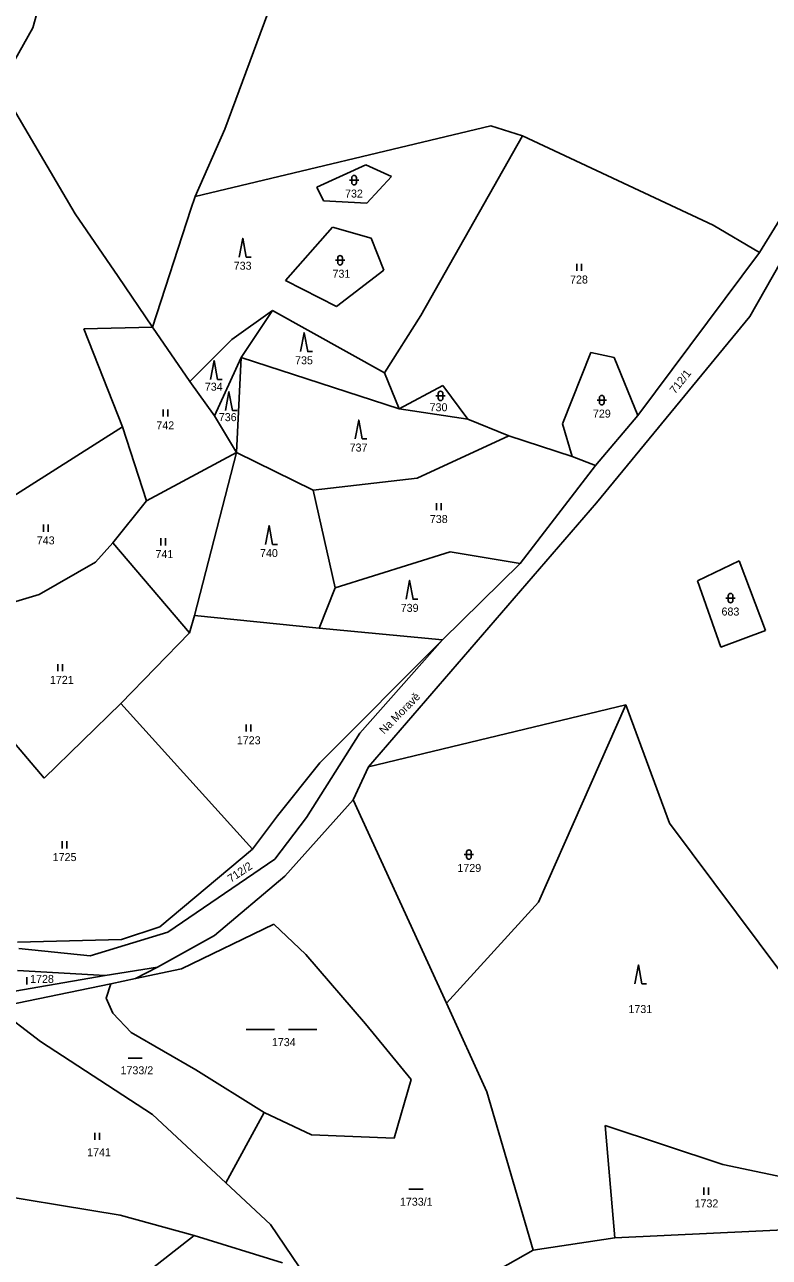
# Model space of a CAD drawing. Extents: x -670359 to -668019, y -978807 to -976674.
# Drawn here: x -668799.4 to -668641.1, y -978050.6 to -977788.7 of the extents above; entities that cross this region are included whole.
import ezdxf

# ---------------------------------------------------------------- set-up
doc = ezdxf.new("R2010")
doc.units = 0
for name, color, linetype in [('Hranice kat_území', 7, 'Continuous'), ('Hranice parcel', 7, 'Continuous'), ('Parcelní čísla', 7, 'Continuous'), ('Pop  PČ popisy', 7, 'Continuous'), ('Značky kultur', 7, 'Continuous')]:
    doc.layers.add(name, color=color, linetype=linetype)

msp = doc.modelspace()

# ---------------------------------------------------------------- linework, layer by layer
at = {"layer": 'Hranice kat_území'}
for points in [[(-668673.95, -978046.48), (-668633.57, -978044.55)], [(-668691.36, -978049.13), (-668673.95, -978046.48)], [(-668717.71, -978064.03), (-668691.36, -978049.13)]]:
    msp.add_lwpolyline(points, dxfattribs=at)
at = {"layer": 'Hranice parcel'}
for points in [[(-668793.42, -977774.28), (-668797.64, -977789.39)], [(-668743.95, -977776.09), (-668756.86, -977810.95)], [(-668797.64, -977789.39), (-668804.65, -977801.77)], [(-668804.65, -977801.77), (-668788.64, -977828.94)], [(-668763.15, -977825.26), (-668700.35, -977810.2)], [(-668756.86, -977810.95), (-668763.15, -977825.26)], [(-668700.35, -977810.2), (-668693.6, -977812.35)], [(-668693.6, -977812.35), (-668715.21, -977850.5)], [(-668693.6, -977812.35), (-668653.1, -977831.31)], [(-668737.3, -977823.25), (-668726.9, -977818.5)], [(-668726.9, -977818.5), (-668721.45, -977820.95)], [(-668721.45, -977820.95), (-668726.65, -977826.65)], [(-668735.85, -977826.15), (-668737.3, -977823.25)], [(-668764.06, -977827.89), (-668763.15, -977825.26)], [(-668726.65, -977826.65), (-668735.85, -977826.15)], [(-668636.27, -977825.84), (-668643.27, -977837.1)], [(-668772.17, -977852.97), (-668779.51, -977842.25), (-668788.64, -977828.94)], [(-668772.17, -977852.97), (-668764.06, -977827.89)], [(-668743.93, -977843.06), (-668733.97, -977831.73)], [(-668733.97, -977831.73), (-668725.73, -977834.07)], [(-668653.1, -977831.31), (-668643.27, -977837.1)], [(-668725.73, -977834.07), (-668723.03, -977840.88)], [(-668643.27, -977837.1), (-668669.09, -977871.75)], [(-668645.3, -977850.7), (-668638.79, -977839.27)], [(-668723.03, -977840.88), (-668733.14, -977848.61)], [(-668733.14, -977848.61), (-668743.93, -977843.06)], [(-668746.68, -977849.45), (-668755.34, -977855.59)], [(-668753.36, -977859.44), (-668746.68, -977849.45)], [(-668746.68, -977849.45), (-668722.94, -977862.72)], [(-668715.21, -977850.5), (-668722.94, -977862.72)], [(-668677.85, -977890.29), (-668645.3, -977850.7)], [(-668772.17, -977852.97), (-668786.8, -977853.34)], [(-668786.8, -977853.34), (-668778.55, -977874.17)], [(-668772.17, -977852.97), (-668764.26, -977864.53)], [(-668755.34, -977855.59), (-668764.26, -977864.53)], [(-668685.11, -977873.55), (-668679.05, -977858.36)], [(-668679.05, -977858.36), (-668674.09, -977859.42)], [(-668753.36, -977859.44), (-668759, -977871.82)], [(-668754.38, -977879.6), (-668753.36, -977859.44)], [(-668753.36, -977859.44), (-668719.76, -977870.33)], [(-668674.09, -977859.42), (-668669.09, -977871.75)], [(-668722.94, -977862.72), (-668719.76, -977870.33)], [(-668764.26, -977864.53), (-668759, -977871.82)], [(-668719.76, -977870.33), (-668710.54, -977865.4)], [(-668710.54, -977865.4), (-668705.2, -977872.53)], [(-668719.76, -977870.33), (-668705.2, -977872.53)], [(-668818.99, -977899.82), (-668778.55, -977874.17)], [(-668778.55, -977874.17), (-668773.47, -977889.86)], [(-668759, -977871.82), (-668754.38, -977879.6)], [(-668705.2, -977872.53), (-668696.48, -977876.08)], [(-668683.05, -977880.51), (-668685.11, -977873.55)], [(-668669.09, -977871.75), (-668678.09, -977882.37)], [(-668715.97, -977885.06), (-668696.48, -977876.08)], [(-668696.48, -977876.08), (-668683.05, -977880.51)], [(-668773.47, -977889.86), (-668754.38, -977879.6)], [(-668754.38, -977879.6), (-668763.31, -977914.29)], [(-668754.38, -977879.6), (-668738.08, -977887.64)], [(-668683.05, -977880.51), (-668678.09, -977882.37)], [(-668678.09, -977882.37), (-668694.09, -977903.2)], [(-668738.08, -977887.64), (-668715.97, -977885.06)], [(-668773.47, -977889.86), (-668780.63, -977898.8)], [(-668738.08, -977887.64), (-668733.42, -977908.38)], [(-668726.28, -977946.45), (-668677.85, -977890.29)], [(-668780.63, -977898.8), (-668784.33, -977902.95)], [(-668764.36, -977917.97), (-668780.63, -977898.8)], [(-668784.33, -977902.95), (-668796.28, -977909.8)], [(-668733.42, -977908.38), (-668708.98, -977900.76)], [(-668708.98, -977900.76), (-668694.09, -977903.2)], [(-668656.41, -977906.89), (-668647.53, -977902.64)], [(-668647.53, -977902.64), (-668641.97, -977917.48)], [(-668694.09, -977903.2), (-668710.56, -977919.4)], [(-668733.42, -977908.38), (-668736.81, -977916.93)], [(-668651.46, -977920.99), (-668656.41, -977906.89)], [(-668796.28, -977909.8), (-668818.56, -977916.46)], [(-668763.31, -977914.29), (-668764.36, -977917.97)], [(-668736.81, -977916.93), (-668763.31, -977914.29)], [(-668764.36, -977917.97), (-668778.92, -977932.96)], [(-668710.56, -977919.4), (-668736.81, -977916.93)], [(-668641.97, -977917.48), (-668651.46, -977920.99)], [(-668710.56, -977919.4), (-668736.63, -977945.54)], [(-668728.17, -977939.29), (-668710.56, -977919.4)], [(-668778.92, -977932.96), (-668795.2, -977948.83)], [(-668778.92, -977932.96), (-668750.96, -977963.93)], [(-668671.67, -977933.25), (-668726.28, -977946.45)], [(-668671.67, -977933.25), (-668690.16, -977975.16)], [(-668671.67, -977933.25), (-668662.34, -977958.37)], [(-668795.2, -977948.83), (-668806.66, -977935.37)], [(-668739.51, -977957.21), (-668728.17, -977939.29)], [(-668736.63, -977945.54), (-668745.63, -977956.82)], [(-668726.28, -977946.45), (-668729.57, -977953.43)], [(-668729.57, -977953.43), (-668744.09, -977969.65)], [(-668709.74, -977996.65), (-668729.57, -977953.43)], [(-668745.63, -977956.82), (-668750.96, -977963.93)], [(-668746.24, -977966.01), (-668739.51, -977957.21)], [(-668662.34, -977958.37), (-668619.62, -978015.52)], [(-668750.96, -977963.93), (-668770.61, -977980.38)], [(-668768.91, -977981.53), (-668746.24, -977966.01)], [(-668744.09, -977969.65), (-668759.04, -977982.26)], [(-668690.16, -977975.16), (-668709.74, -977996.65)], [(-668785.48, -977986.54), (-668768.91, -977981.53)], [(-668770.61, -977980.38), (-668778.82, -977983.12)], [(-668766.04, -977989.34), (-668746.43, -977979.85)], [(-668746.43, -977979.85), (-668739.66, -977986.29)], [(-668778.82, -977983.12), (-668800.92, -977983.69)], [(-668759.04, -977982.26), (-668771.16, -977989.01)], [(-668800.6, -977985.03), (-668785.48, -977986.54)], [(-668739.66, -977986.29), (-668726.95, -978000.99)], [(-668771.16, -977989.01), (-668782.24, -977990.74)], [(-668775.85, -977991.41), (-668771.16, -977989.01)], [(-668775.85, -977991.41), (-668766.04, -977989.34)], [(-668782.24, -977990.74), (-668801.42, -977994.08)], [(-668782.24, -977990.74), (-668800.87, -977989.69)], [(-668781.08, -977992.49), (-668775.85, -977991.41)], [(-668805.49, -977997.52), (-668781.08, -977992.49)], [(-668776.74, -978002.88), (-668780.62, -977998.76), (-668782.03, -977995.6), (-668781.08, -977992.49)], [(-668701.18, -978015.44), (-668709.74, -977996.65)], [(-668796.01, -978004.81), (-668805.49, -977997.52)], [(-668726.95, -978000.99), (-668717.23, -978012.84)], [(-668772.18, -978020.27), (-668796.01, -978004.81)], [(-668762.97, -978010.83), (-668776.74, -978002.88)], [(-668748.48, -978019.89), (-668762.97, -978010.83)], [(-668717.23, -978012.84), (-668720.88, -978025.33)], [(-668691.36, -978049.13), (-668701.18, -978015.44)], [(-668772.18, -978020.27), (-668756.62, -978034.81)], [(-668756.62, -978034.81), (-668748.48, -978019.89)], [(-668738.4, -978024.63), (-668748.48, -978019.89)], [(-668651.02, -978030.89), (-668676.01, -978022.61)], [(-668676.01, -978022.61), (-668673.95, -978046.48)], [(-668720.88, -978025.33), (-668738.4, -978024.63)], [(-668634.2, -978034.46), (-668651.02, -978030.89)], [(-668779.04, -978041.67), (-668811.76, -978036.29)], [(-668747.13, -978043.67), (-668756.62, -978034.81)], [(-668763.34, -978046.02), (-668779.04, -978041.67)], [(-668741.05, -978052.66), (-668747.13, -978043.67)], [(-668763.34, -978046.02), (-668795.8, -978071.45)], [(-668744.55, -978051.8), (-668763.34, -978046.02)]]:
    msp.add_lwpolyline(points, dxfattribs=at)
at = {"layer": 'Značky kultur'}
for p, q in [((-668730.37, -977821.76), (-668728.37, -977821.76)), ((-668729.87, -977821.26), (-668729.87, -977822.26)), ((-668728.87, -977821.26), (-668728.87, -977822.26)), ((-668733.35, -977838.79), (-668731.35, -977838.79)), ((-668732.85, -977838.29), (-668732.85, -977839.29)), ((-668731.85, -977838.29), (-668731.85, -977839.29)), ((-668682.06, -977839.52), (-668682.06, -977841.02)), ((-668681.06, -977841.02), (-668681.06, -977839.52)), ((-668712, -977867.6), (-668710, -977867.6)), ((-668711.5, -977867.1), (-668711.5, -977868.1)), ((-668710.5, -977867.1), (-668710.5, -977868.1)), ((-668677.74, -977868.51), (-668675.74, -977868.51)), ((-668677.24, -977868.01), (-668677.24, -977869.01)), ((-668676.24, -977868.01), (-668676.24, -977869.01)), ((-668769.96, -977870.51), (-668769.96, -977872.01)), ((-668768.96, -977872.01), (-668768.96, -977870.51)), ((-668711.85, -977890.41), (-668711.85, -977891.91)), ((-668710.85, -977891.91), (-668710.85, -977890.41)), ((-668795.36, -977894.95), (-668795.36, -977896.45)), ((-668794.36, -977896.45), (-668794.36, -977894.95)), ((-668770.46, -977897.86), (-668770.46, -977899.36)), ((-668769.46, -977899.36), (-668769.46, -977897.86)), ((-668650.38, -977910.57), (-668648.38, -977910.57)), ((-668649.88, -977910.07), (-668649.88, -977911.07)), ((-668648.88, -977910.07), (-668648.88, -977911.07)), ((-668792.32, -977924.59), (-668792.32, -977926.09)), ((-668791.32, -977926.09), (-668791.32, -977924.59)), ((-668752.29, -977937.42), (-668752.29, -977938.92)), ((-668751.29, -977938.92), (-668751.29, -977937.42)), ((-668791.41, -977962.24), (-668791.41, -977963.74)), ((-668790.41, -977963.74), (-668790.41, -977962.24)), ((-668705.97, -977965.05), (-668703.97, -977965.05)), ((-668705.47, -977964.55), (-668705.47, -977965.55)), ((-668704.47, -977964.55), (-668704.47, -977965.55)), ((-668798.93, -977992.64), (-668798.93, -977991.14)), ((-668752.31, -978002.23), (-668746.31, -978002.23)), ((-668743.31, -978002.23), (-668737.31, -978002.23)), ((-668777.4, -978008.32), (-668774.4, -978008.32)), ((-668784.43, -978024.2), (-668784.43, -978025.7)), ((-668783.43, -978025.7), (-668783.43, -978024.2)), ((-668717.73, -978036.15), (-668714.73, -978036.15)), ((-668655.04, -978035.83), (-668655.04, -978037.33)), ((-668654.04, -978037.33), (-668654.04, -978035.83))]:
    msp.add_line(p, q, dxfattribs=at)
for points in [[(-668753.77, -977838.09), (-668753.02, -977834.09), (-668752.27, -977838.09), (-668751.27, -977838.09)], [(-668740.73, -977858.18), (-668739.98, -977854.18), (-668739.23, -977858.18), (-668738.23, -977858.18)], [(-668759.87, -977864.1), (-668759.12, -977860.1), (-668758.37, -977864.1), (-668757.37, -977864.1)], [(-668756.71, -977870.7), (-668755.96, -977866.7), (-668755.21, -977870.7), (-668754.21, -977870.7)], [(-668729.14, -977876.72), (-668728.39, -977872.72), (-668727.64, -977876.72), (-668726.64, -977876.72)], [(-668748.18, -977899.14), (-668747.43, -977895.14), (-668746.68, -977899.14), (-668745.68, -977899.14)], [(-668718.33, -977910.79), (-668717.58, -977906.79), (-668716.83, -977910.79), (-668715.83, -977910.79)], [(-668669.72, -977992.52), (-668668.97, -977988.52), (-668668.22, -977992.52), (-668667.22, -977992.52)]]:
    msp.add_lwpolyline(points, dxfattribs=at)
for centre, start, end in [((-668729.37, -977821.26), 0, 180), ((-668729.37, -977822.26), 180, 0), ((-668732.35, -977838.29), 0, 180), ((-668732.35, -977839.29), 180, 0), ((-668711, -977867.1), 0, 180), ((-668711, -977868.1), 180, 0), ((-668676.74, -977868.01), 0, 180), ((-668676.74, -977869.01), 180, 0), ((-668649.38, -977910.07), 0, 180), ((-668649.38, -977911.07), 180, 0), ((-668704.97, -977964.55), 0, 180), ((-668704.97, -977965.55), 180, 0)]:
    msp.add_arc(centre, 0.5, start, end, dxfattribs=at)

# ---------------------------------------------------------------- texts
at = {"layer": 'Parcelní čísla'}
for s, p in [('732', (-668731.3, -977825.46)), ('733', (-668754.95, -977840.79)), ('731', (-668733.96, -977842.49)), ('728', (-668683.49, -977843.72)), ('735', (-668741.91, -977860.88)), ('734', (-668761.09, -977866.5)), ('736', (-668758.12, -977872.96)), ('730', (-668713.33, -977870.86)), ('729', (-668678.63, -977872.21)), ('742', (-668771.39, -977874.71)), ('737', (-668730.32, -977879.42)), ('738', (-668713.28, -977894.61)), ('743', (-668796.79, -977899.15)), ('741', (-668771.57, -977902.06)), ('740', (-668749.36, -977901.84)), ('739', (-668719.47, -977913.49)), ('683', (-668651.31, -977914.27)), ('1721', (-668794, -977928.79)), ('1723', (-668754.29, -977941.62)), ('1725', (-668793.41, -977966.44)), ('1729', (-668707.43, -977968.75)), ('1728', (-668798.21, -977992.33)), ('1731', (-668671.09, -977998.73)), ('1734', (-668746.84, -978005.76)), ('1733/2', (-668779, -978011.74)), ('1741', (-668786.09, -978029.16)), ('1733/1', (-668719.64, -978039.67)), ('1732', (-668657.04, -978040.03))]:
    msp.add_text(s, height=1.7, dxfattribs=at).set_placement(p)
for s, rotation, p in [('712/1', 51.783, (-668661.16, -977867.31)), ('712/2', 33.7242, (-668755.53, -977971.07))]:
    msp.add_text(s, height=1.7, rotation=rotation, dxfattribs=at).set_placement(p)
at = {"layer": 'Pop  PČ popisy'}
msp.add_text('Na Moravě', height=1.7, rotation=45.4268, dxfattribs=at).set_placement((-668722.99, -977939.58))

doc.saveas('drawing.dxf')
